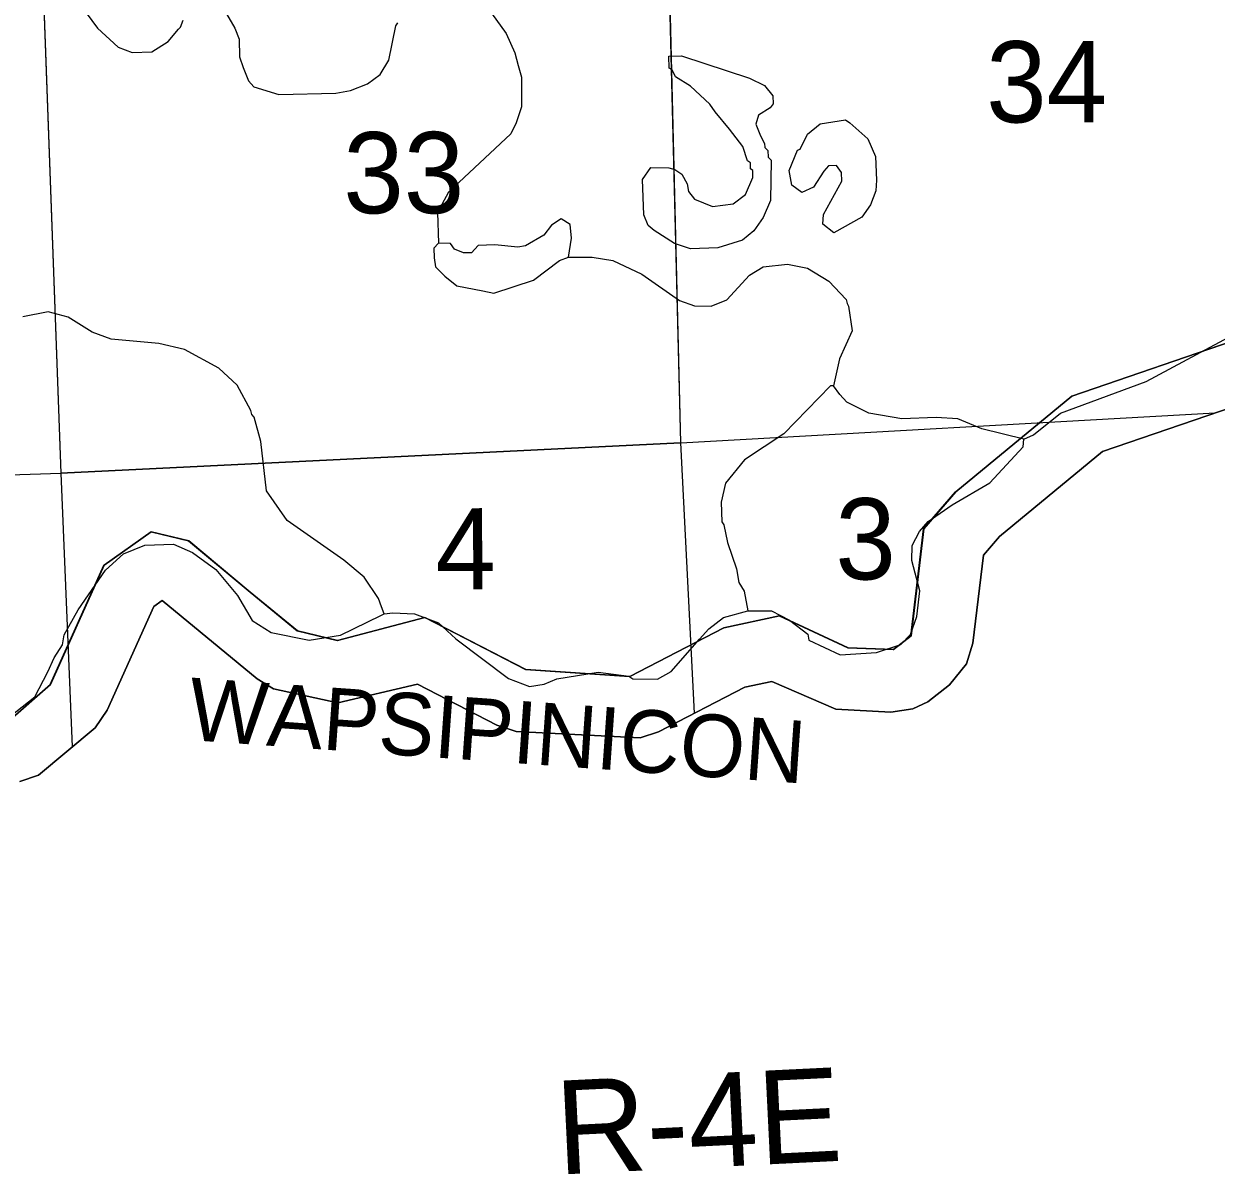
# Model space of a CAD drawing. Extents: x 128.7 to 185.5, y -21.4 to 12.6.
# Drawn here: x 154.322 to 156.23, y -14.212 to -12.371 of the extents above; entities that cross this region are included whole.
import ezdxf

# ---------------------------------------------------------------- set-up
doc = ezdxf.new("R2010")
doc.units = 0
for name, color, linetype in [('tdCoClipBndry', 7, 'Continuous'), ('tdCoCoBndry', 7, 'Continuous'), ('tdCoCoBndryPart', 7, 'Continuous'), ('tdCoHydroRiver', 7, 'Continuous'), ('tdCoHydroTxtLg', 7, 'Continuous'), ('tdCoSectLine', 7, 'Continuous'), ('tdCoSectLinePart', 7, 'Continuous'), ('tdCoSectNmbr', 7, 'Continuous'), ('tdCoTwpBndryShd', 7, 'Continuous'), ('tdCoTwpRngTxt', 7, 'Continuous')]:
    doc.layers.add(name, color=color, linetype=linetype)

msp = doc.modelspace()

# ---------------------------------------------------------------- linework, layer by layer
at = {"layer": 'tdCoClipBndry'}
msp.add_lwpolyline([(156.2993, -12.9695), (156.0482, -13.0555), (155.8832, -13.1916), (155.8576, -13.2212), (155.8407, -13.3622), (155.8308, -13.3953), (155.8036, -13.4286), (155.7685, -13.456), (155.7446, -13.4674), (155.7098, -13.4723), (155.6215, -13.4678), (155.519, -13.4233), (155.4761, -13.4324), (155.3376, -13.504), (155.3083, -13.5138), (155.1103, -13.5033), (155.0791, -13.4932), (154.952, -13.4275), (154.8248, -13.4575), (154.722, -13.4351), (154.6958, -13.4194), (154.544, -13.2937), (154.5306, -13.3032), (154.4556, -13.4694), (154.4365, -13.4976), (154.346, -13.5734), (154.3158, -13.5834)], dxfattribs=at)
at = {"layer": 'tdCoCoBndry'}
for p, q in [((156.2812, -12.8702), (155.999, -12.9668)), ((155.999, -12.9668), (156.2812, -12.8702)), ((155.999, -12.9668), (155.8135, -13.1199)), ((155.8135, -13.1199), (155.999, -12.9668)), ((155.8135, -13.1199), (155.7624, -13.179)), ((155.7624, -13.179), (155.8135, -13.1199)), ((155.7624, -13.179), (155.7419, -13.3503)), ((155.7419, -13.3503), (155.7624, -13.179)), ((154.5262, -13.1838), (154.451, -13.2375)), ((154.451, -13.2375), (154.5262, -13.1838)), ((154.5863, -13.1986), (154.5262, -13.1838)), ((154.5262, -13.1838), (154.5863, -13.1986)), ((154.6847, -13.2806), (154.5863, -13.1986)), ((154.5863, -13.1986), (154.6847, -13.2806)), ((154.451, -13.2375), (154.3649, -13.4283)), ((154.3649, -13.4283), (154.451, -13.2375)), ((154.76, -13.3425), (154.6847, -13.2806)), ((154.6847, -13.2806), (154.76, -13.3425)), ((154.9642, -13.3211), (154.8241, -13.3576)), ((154.8241, -13.3576), (154.9642, -13.3211)), ((155.1254, -13.4044), (154.9642, -13.3211)), ((154.9642, -13.3211), (155.1254, -13.4044)), ((155.5312, -13.3186), (155.4425, -13.3374)), ((155.4425, -13.3374), (155.5312, -13.3186)), ((155.6414, -13.3697), (155.5312, -13.3186)), ((155.5312, -13.3186), (155.6414, -13.3697)), ((154.8241, -13.3576), (154.76, -13.3425)), ((154.76, -13.3425), (154.8241, -13.3576)), ((155.4425, -13.3374), (155.292, -13.4153)), ((155.292, -13.4153), (155.4425, -13.3374)), ((155.7419, -13.3503), (155.7139, -13.3724)), ((155.7139, -13.3724), (155.7419, -13.3503)), ((155.7139, -13.3724), (155.6414, -13.3697)), ((155.6414, -13.3697), (155.7139, -13.3724)), ((155.292, -13.4153), (155.1254, -13.4044)), ((155.1254, -13.4044), (155.292, -13.4153)), ((154.3649, -13.4283), (154.3004, -13.4847)), ((154.3004, -13.4847), (154.3649, -13.4283))]:
    msp.add_line(p, q, dxfattribs=at)
for points in [[(154.3, -13.4847), (154.3645, -13.4283), (154.4506, -13.2375), (154.5259, -13.1838), (154.586, -13.1986), (154.6844, -13.2806), (154.7596, -13.3425), (154.8237, -13.3576), (154.9638, -13.3211), (155.125, -13.4044), (155.2916, -13.4153), (155.4422, -13.3374), (155.5308, -13.3186), (155.641, -13.3697), (155.7135, -13.3724), (155.7415, -13.3503), (155.762, -13.179), (155.8131, -13.1199), (155.9986, -12.9668), (156.2808, -12.8702)], [(156.2812, -12.8702), (155.999, -12.9668), (155.8135, -13.1199), (155.7624, -13.179), (155.7419, -13.3503), (155.7139, -13.3724), (155.6414, -13.3697), (155.5312, -13.3186), (155.4425, -13.3374), (155.292, -13.4153), (155.1254, -13.4044), (154.9642, -13.3211), (154.8241, -13.3576), (154.76, -13.3425), (154.6847, -13.2806), (154.5863, -13.1986), (154.5262, -13.1838), (154.451, -13.2375), (154.3649, -13.4283), (154.3004, -13.4847)], [(156.2812, -12.8702), (155.999, -12.9668), (155.8135, -13.1199), (155.7624, -13.179), (155.7419, -13.3503), (155.7139, -13.3724), (155.6414, -13.3697), (155.5312, -13.3186), (155.4425, -13.3374), (155.292, -13.4153), (155.1254, -13.4044), (154.9642, -13.3211), (154.8241, -13.3576), (154.76, -13.3425), (154.6847, -13.2806), (154.5863, -13.1986), (154.5262, -13.1838), (154.451, -13.2375), (154.3649, -13.4283), (154.3004, -13.4847)], [(154.3158, -13.5834), (154.346, -13.5734), (154.4365, -13.4976), (154.4556, -13.4694), (154.5306, -13.3032), (154.544, -13.2937), (154.6958, -13.4194), (154.722, -13.4351), (154.8248, -13.4575), (154.952, -13.4275), (155.0791, -13.4932), (155.1103, -13.5033), (155.3083, -13.5138), (155.3376, -13.504), (155.4761, -13.4324), (155.519, -13.4233), (155.6215, -13.4678), (155.7098, -13.4723), (155.7446, -13.4674), (155.7685, -13.456), (155.8036, -13.4286), (155.8308, -13.3953), (155.8407, -13.3622), (155.8576, -13.2212), (155.8832, -13.1916), (156.0482, -13.0555), (156.2993, -12.9695)]]:
    msp.add_lwpolyline(points, dxfattribs=at)
at = {"layer": 'tdCoCoBndryPart'}
msp.add_lwpolyline([(154.3, -13.4847), (154.3645, -13.4283), (154.4506, -13.2375), (154.5259, -13.1838), (154.586, -13.1986), (154.6844, -13.2806), (154.7596, -13.3425), (154.8237, -13.3576), (154.9638, -13.3211), (155.125, -13.4044), (155.2916, -13.4153), (155.4422, -13.3374), (155.5308, -13.3186), (155.641, -13.3697), (155.7135, -13.3724), (155.7415, -13.3503), (155.762, -13.179), (155.8131, -13.1199), (155.9986, -12.9668), (156.2808, -12.8702)], dxfattribs=at)
at = {"layer": 'tdCoHydroRiver'}
for points in [[(154.404, -12.3285), (154.4404, -12.3778), (154.4731, -12.4082), (154.4955, -12.4169), (154.527, -12.4159), (154.5532, -12.3992), (154.5699, -12.3797), (154.573, -12.3764), (154.5773, -12.3652)], [(154.6431, -12.3487), (154.6599, -12.3781), (154.6668, -12.3953), (154.6677, -12.4236), (154.6731, -12.4408), (154.682, -12.4624), (154.6903, -12.4715), (154.7306, -12.484), (154.8215, -12.4818), (154.8453, -12.4776), (154.872, -12.467), (154.8924, -12.4518), (154.9062, -12.4289), (154.9178, -12.3741), (154.9209, -12.3692)], [(155.0708, -12.354), (155.094, -12.3864), (155.1078, -12.4174), (155.1132, -12.4378), (155.1186, -12.4565), (155.1187, -12.5039), (155.1102, -12.5294), (155.1014, -12.5471), (155.0021, -12.6406), (154.9843, -12.6728), (154.9861, -12.7217), (154.9785, -12.7299), (154.979, -12.7456), (154.9811, -12.7598), (154.9959, -12.775), (155.0153, -12.7901), (155.0567, -12.7981), (155.0742, -12.8022), (155.1381, -12.781), (155.1796, -12.7495), (155.1936, -12.7443), (155.2315, -12.7445), (155.2649, -12.7496), (155.3114, -12.7716), (155.3713, -12.8137), (155.3953, -12.8223), (155.4222, -12.8229), (155.4471, -12.8126), (155.4835, -12.7734), (155.5052, -12.76), (155.5445, -12.7554), (155.5763, -12.7622), (155.6102, -12.783), (155.638, -12.812), (155.6398, -12.8183), (155.6416, -12.823), (155.6477, -12.8622), (155.6272, -12.9071), (155.6177, -12.9501), (155.613, -12.9503), (155.5384, -13.0271), (155.4752, -13.0688), (155.445, -13.1062), (155.4381, -13.1365), (155.4393, -13.168), (155.4426, -13.1726), (155.4483, -13.2008), (155.4625, -13.2429), (155.4664, -13.2649), (155.4748, -13.2788), (155.4807, -13.3102)], [(155.433, -12.7294), (155.3889, -12.731), (155.3633, -12.7224), (155.331, -12.7015), (155.3213, -12.6939), (155.3144, -12.6768), (155.3123, -12.6201), (155.3258, -12.6006), (155.3543, -12.6012), (155.3638, -12.604), (155.3752, -12.6115), (155.3836, -12.627), (155.3856, -12.6395), (155.3955, -12.6518), (155.4244, -12.6634), (155.4574, -12.6591), (155.4773, -12.6442), (155.489, -12.6169), (155.4886, -12.6059), (155.4853, -12.6028), (155.485, -12.5934), (155.4802, -12.5904), (155.473, -12.567), (155.4515, -12.5393), (155.4284, -12.5117), (155.4201, -12.4994), (155.389, -12.4705), (155.3648, -12.4556), (155.3597, -12.4447), (155.3549, -12.4418), (155.3542, -12.4228), (155.3747, -12.4221), (155.4833, -12.4577), (155.5074, -12.4694), (155.5206, -12.4863), (155.5211, -12.4989), (155.5166, -12.5054), (155.4981, -12.5171), (155.4938, -12.5315), (155.5008, -12.5502), (155.5076, -12.5626), (155.5078, -12.5689), (155.5127, -12.5734), (155.5131, -12.5845), (155.518, -12.589), (155.5172, -12.6538), (155.5055, -12.681), (155.4905, -12.7021), (155.4721, -12.7169), (155.433, -12.7294)], [(155.6184, -12.7054), (155.6006, -12.6918), (155.6016, -12.676), (155.6313, -12.6229), (155.6308, -12.6087), (155.6225, -12.5979), (155.6099, -12.5984), (155.6023, -12.6065), (155.5858, -12.6324), (155.5672, -12.6409), (155.551, -12.6289), (155.547, -12.6054), (155.56, -12.5733), (155.5647, -12.5716), (155.5765, -12.5475), (155.5964, -12.531), (155.6372, -12.5248), (155.6437, -12.5293), (155.673, -12.5551), (155.6851, -12.583), (155.6864, -12.6209), (155.6855, -12.6383), (155.6768, -12.6607), (155.6633, -12.6801), (155.6184, -12.7054)], [(155.1936, -12.7443), (155.1989, -12.7141), (155.1965, -12.6921), (155.182, -12.6831), (155.1666, -12.6932), (155.1545, -12.7094), (155.1251, -12.7262), (155.1126, -12.7282), (155.0761, -12.7248), (155.0493, -12.7258), (155.0387, -12.7372), (155.0261, -12.7376), (155.0117, -12.7318), (155.005, -12.7226), (154.9861, -12.7217)], [(154.8988, -13.3154), (154.8948, -13.304), (154.89, -13.2905), (154.8668, -13.2565), (154.8343, -13.2292), (154.7437, -13.166), (154.7105, -13.1183), (154.7015, -13.0396), (154.6907, -13.0006), (154.6874, -12.9959), (154.6856, -12.9897), (154.6637, -12.9494), (154.6343, -12.922), (154.5796, -12.8923), (154.5383, -12.8827), (154.4623, -12.8758), (154.4319, -12.8642), (154.3932, -12.8403), (154.3613, -12.8319), (154.3206, -12.8396)], [(154.2891, -13.4879), (154.3399, -13.4482), (154.3606, -13.4081), (154.3709, -13.3856), (154.3843, -13.3646), (154.387, -13.3488), (154.4093, -13.3085), (154.4529, -13.2455), (154.4819, -13.2192), (154.5162, -13.2054), (154.5619, -13.2039), (154.5924, -13.217), (154.6296, -13.2442), (154.6642, -13.2856), (154.6876, -13.3258), (154.7183, -13.3453), (154.7787, -13.3574), (154.8289, -13.3494), (154.8936, -13.318), (154.8988, -13.3154), (154.9126, -13.3138), (154.9473, -13.315), (154.9857, -13.3294), (155.0135, -13.3553), (155.0978, -13.4186), (155.1314, -13.4316), (155.155, -13.4276), (155.1752, -13.419), (155.2411, -13.4087), (155.2903, -13.4148), (155.2967, -13.4193), (155.3362, -13.4195), (155.3579, -13.4077), (155.4034, -13.3555), (155.4186, -13.3392), (155.4416, -13.321), (155.4807, -13.3102), (155.5186, -13.3104), (155.5475, -13.3251), (155.5767, -13.3478), (155.5786, -13.3572), (155.6284, -13.3806), (155.6867, -13.377), (155.7257, -13.3645), (155.7409, -13.3482), (155.7509, -13.3194), (155.7558, -13.2782), (155.743, -13.2297), (155.7437, -13.206), (155.7555, -13.1835), (155.7691, -13.1672), (155.8077, -13.1406), (155.868, -13.1053), (155.9212, -13.0481), (155.9223, -13.0355), (155.9378, -13.0286), (155.9808, -12.9939), (156.1179, -12.9432), (156.2573, -12.8688)], [(155.9223, -13.0355), (155.8554, -13.0189), (155.8169, -13.0029), (155.7821, -13.001), (155.727, -13.003), (155.6745, -12.9938), (155.6392, -12.9762), (155.6277, -12.9639), (155.6177, -12.9501)]]:
    msp.add_lwpolyline(points, dxfattribs=at)
at = {"layer": 'tdCoSectLine'}
for points in [[(155.3736, -13.0416), (155.3484, -12.0277)], [(155.3484, -12.0277), (155.3733, -13.0416)], [(154.3445, -12.0662), (154.3818, -13.0902)], [(155.3736, -13.0416), (156.2285, -12.9937)], [(155.3733, -13.0416), (154.3818, -13.0902)], [(154.3818, -13.0902), (155.3733, -13.0417)], [(155.3733, -13.0416), (155.3736, -13.0416)], [(155.3733, -13.0417), (155.3736, -13.0417), (155.3736, -13.0416)], [(155.3733, -13.0416), (155.3733, -13.0417)], [(155.3733, -13.0417), (155.3948, -13.4744)], [(153.6612, -13.1133), (154.3818, -13.0902)], [(154.3818, -13.0902), (154.4, -13.5282)]]:
    msp.add_lwpolyline(points, dxfattribs=at)
at = {"layer": 'tdCoSectLinePart'}
for points in [[(155.3736, -13.0416), (155.3491, -12.0576)], [(155.3491, -12.0576), (155.3733, -13.0416)], [(154.3455, -12.0941), (154.3818, -13.0902)], [(155.3736, -13.0416), (156.2285, -12.9937)], [(155.3733, -13.0416), (154.3818, -13.0902)], [(154.3818, -13.0902), (155.3733, -13.0417)], [(155.3733, -13.0416), (155.3736, -13.0416)], [(155.3733, -13.0417), (155.3736, -13.0417), (155.3736, -13.0416)], [(155.3733, -13.0416), (155.3733, -13.0417)], [(155.3733, -13.0417), (155.3948, -13.4744)], [(153.6612, -13.1133), (154.3818, -13.0902)], [(154.3818, -13.0902), (154.4, -13.5282)]]:
    msp.add_lwpolyline(points, dxfattribs=at)
at = {"layer": 'tdCoTwpBndryShd'}
msp.add_lwpolyline([(154.3, -13.4847), (154.3645, -13.4283), (154.4506, -13.2375), (154.5259, -13.1838), (154.586, -13.1986), (154.6844, -13.2806), (154.7596, -13.3425), (154.8237, -13.3576), (154.9638, -13.3211), (155.125, -13.4044), (155.2916, -13.4153), (155.4422, -13.3374), (155.5308, -13.3186), (155.641, -13.3697), (155.7135, -13.3724), (155.7415, -13.3503), (155.762, -13.179), (155.8131, -13.1199), (155.9986, -12.9668), (156.2808, -12.8702)], dxfattribs=at)

# ---------------------------------------------------------------- texts
at = {"layer": 'tdCoHydroTxtLg'}
msp.add_text('WAPSIPINICON', height=0.1, rotation=355.9457, dxfattribs=at).set_placement((154.5835, -13.5169))
at = {"layer": 'tdCoSectNmbr'}
for s, rotation, p in [('34', 0.1171, (155.8622, -12.5288)), ('33', 0.1167, (154.8337, -12.6743)), ('3', 0.1179, (155.6209, -13.2602)), ('4', 0.1179, (154.9811, -13.2762))]:
    msp.add_text(s, height=0.13, rotation=rotation, dxfattribs=at).set_placement(p)
at = {"layer": 'tdCoTwpRngTxt'}
msp.add_text('R-4E', height=0.15, rotation=2.8064, dxfattribs=at).set_placement((155.1772, -14.2127))

doc.saveas('drawing.dxf')
